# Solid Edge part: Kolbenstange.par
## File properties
Username: bmolnar
Dokumentum tartalom típus: 0
Author: bmolnar
Last saved by: bmolnar
Revision: 90
Sűrűség: 0,000 kg/m^3
Pontosság: 0,990
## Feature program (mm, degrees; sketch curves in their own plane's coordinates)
base feature "unnamed BaseFeature 1"
thread "unnamed Thread 1"
sketch for "unnamed Protrusion 1" plane through (0, 0, -18.3) normal (0, 0, -1) x-axis (0, -1, 0)
  circle centre (0, 0) radius 10
extrude "unnamed Protrusion 1" add finite 6.7 along +normal
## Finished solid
Body 1: solid body, 17 faces, 23 edges, 8 vertices.
  Faces by surface: plane 8, cylinder 4, torus 3, cone 2
  Edges by curve: circle 13, line 6, ellipse 2, intersection 2
Bounding box of the edges (mm; curved faces can reach further): 20.000 x 20.000 x 166.000, from (-10, -10, -25) to (10, 10, 141).
Cylindrical faces by radius (mm): R2.9 x1, R4 x1, R5 x1, R10 x1
Conical faces (half-angle, radius in mm at the cone's reference point): 20 deg R3.5 x1, 60 deg R3.55 x1
Toroidal faces (ring radius, tube radius in mm): R3.3 r0.4 x2, R3.8 r1.2 x1
Planar faces by outward normal: +x 1, +z 3, -x 1, -z 1, oblique 2
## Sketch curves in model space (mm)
circle centre (0, 0, -18.3) radius 10
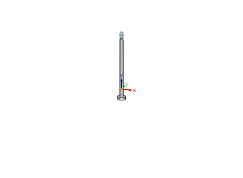
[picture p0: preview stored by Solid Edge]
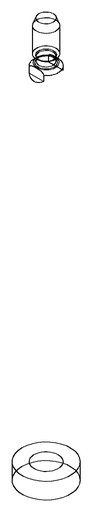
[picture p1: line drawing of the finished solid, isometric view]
